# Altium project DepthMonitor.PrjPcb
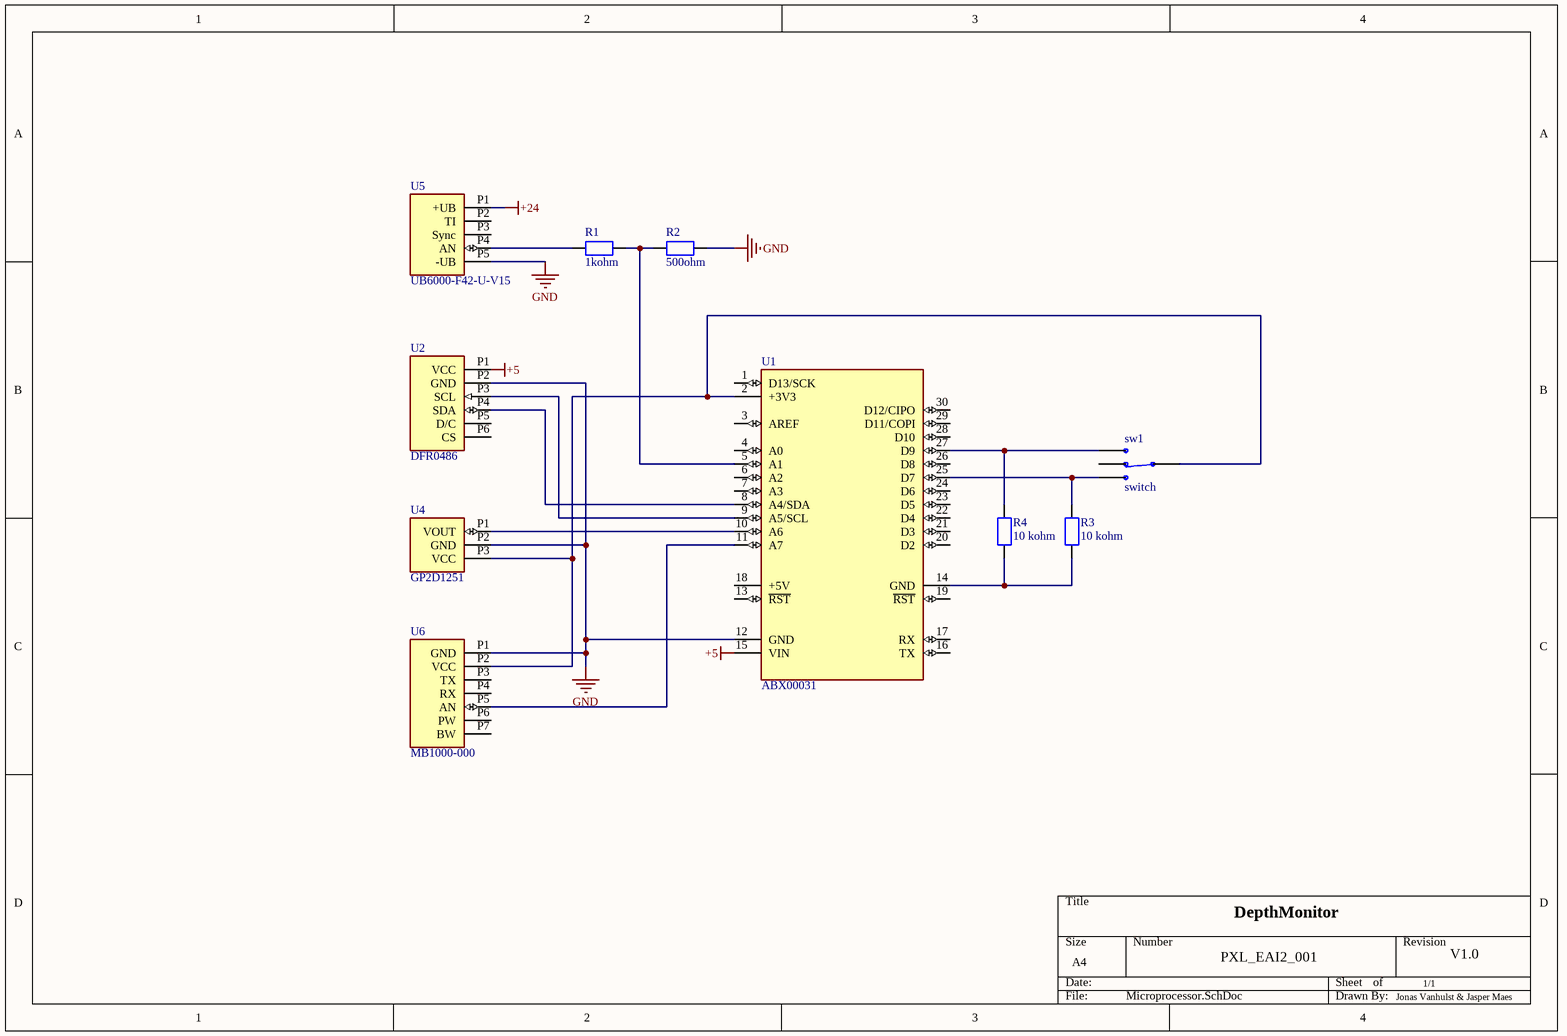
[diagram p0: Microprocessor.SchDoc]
1 sheet, 10 parts. Net scope: global (net labels, ports and power ports of the same name join across sheets).

## Sheet Microprocessor.SchDoc
size A4; SheetNumber: 1; SheetTotal: 1

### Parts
R1  1kohm  [Weerstand 1M ohm]
R2  500ohm  [Weerstand 1M ohm]
R3  10 kohm  [Weerstand 1M ohm]
R4  10 kohm  [Weerstand 1M ohm]
sw1  switch
U1  ABX00031  [MODULE_ABX00030]
U2  DFR0486  [GP2DXX]
U4  GP2D1251  [GP2DXX]
U5  UB6000-F42-U-V15  [GP2DXX]
U6  MB1000-000  [GP2DXX]

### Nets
+5: U1.15(VIN) U2.P1(VCC)
+24: U5.P1(+UB)
GND: R2.2 U1.12(GND) U2.P2(GND) U4.P2(GND) U5.P5(-UB) U6.P1(GND)
NetR1_1: R1.1 U5.P4(AN)
NetR1_2: R1.2 R2.1 U1.5(A1)
NetR3_1: R3.1 R4.1 U1.14(GND)
NetR3_2: R3.2 sw1.?2 U1.25(D7)
NetR4_2: R4.2 sw1.?3 U1.27(D9)
Netsw1_?4: sw1.?4 U1.2(+3V3) U4.P3(VCC) U6.P2(VCC)
NetU1_8: U1.8(A4/SDA) U2.P4(SDA)
NetU1_9: U1.9(A5/SCL) U2.P3(SCL)
NetU1_10: U1.10(A6) U4.P1(VOUT)
NetU1_11: U1.11(A7) U6.P5(AN)

Not connected (* = marked no-connect by the designer): sw1 ?1; U1 1(D13/SCK) 3(AREF) 4(A0) 6(A2) 7(A3) 13(~{RST}) 16(TX) 17(RX) 18(+5V) 19(~{RST}) 20(D2) 21(D3) 22(D4) 23(D5) 24(D6) 26(D8) 28(D10) 29(D11/COPI) 30(D12/CIPO); U2 P5(D/C) P6(CS); U5 P2(TI) P3(Sync); U6 P3(TX) P4(RX) P6(PW) P7(BW)

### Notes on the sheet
- DepthMonitor
- PXL_EAI2_001
- 1/1
- V1.0
- Jonas Vanhulst & Jasper Maes

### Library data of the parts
R1 = Weerstand 1 kohm: Manufacturer: Vishay Dale; Part Number: CRCW0805100RFKEA
R2 = Weerstand 500 ohm: Manufacturer: Vishay Dale; Part Number: CRCW0805100RFKEA
R3 R4 = Weerstand 10 kohm: Manufacturer: Vishay Dale; Part Number: CRCW0805100RFKEA
U1 = ABX00031: Arduino Nano 33 BLE; MP: ABX00030
U2 = DFR0486: 0.96" 128x64 OLED(V1.0) display DFROBOT; MP: GP2D120; MF: Sharp
U4 = GP2D1251: SENSOR OPTICAL ANALOG; MP: GP2D120; MF: Sharp
U5 = UB6000-F42-U-V15: Ultrasonic sensor; MP: GP2D120; MF: Sharp
U6 = MB1000-000: Analog ultrasonic sensor; MP: GP2D120; MF: Sharp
